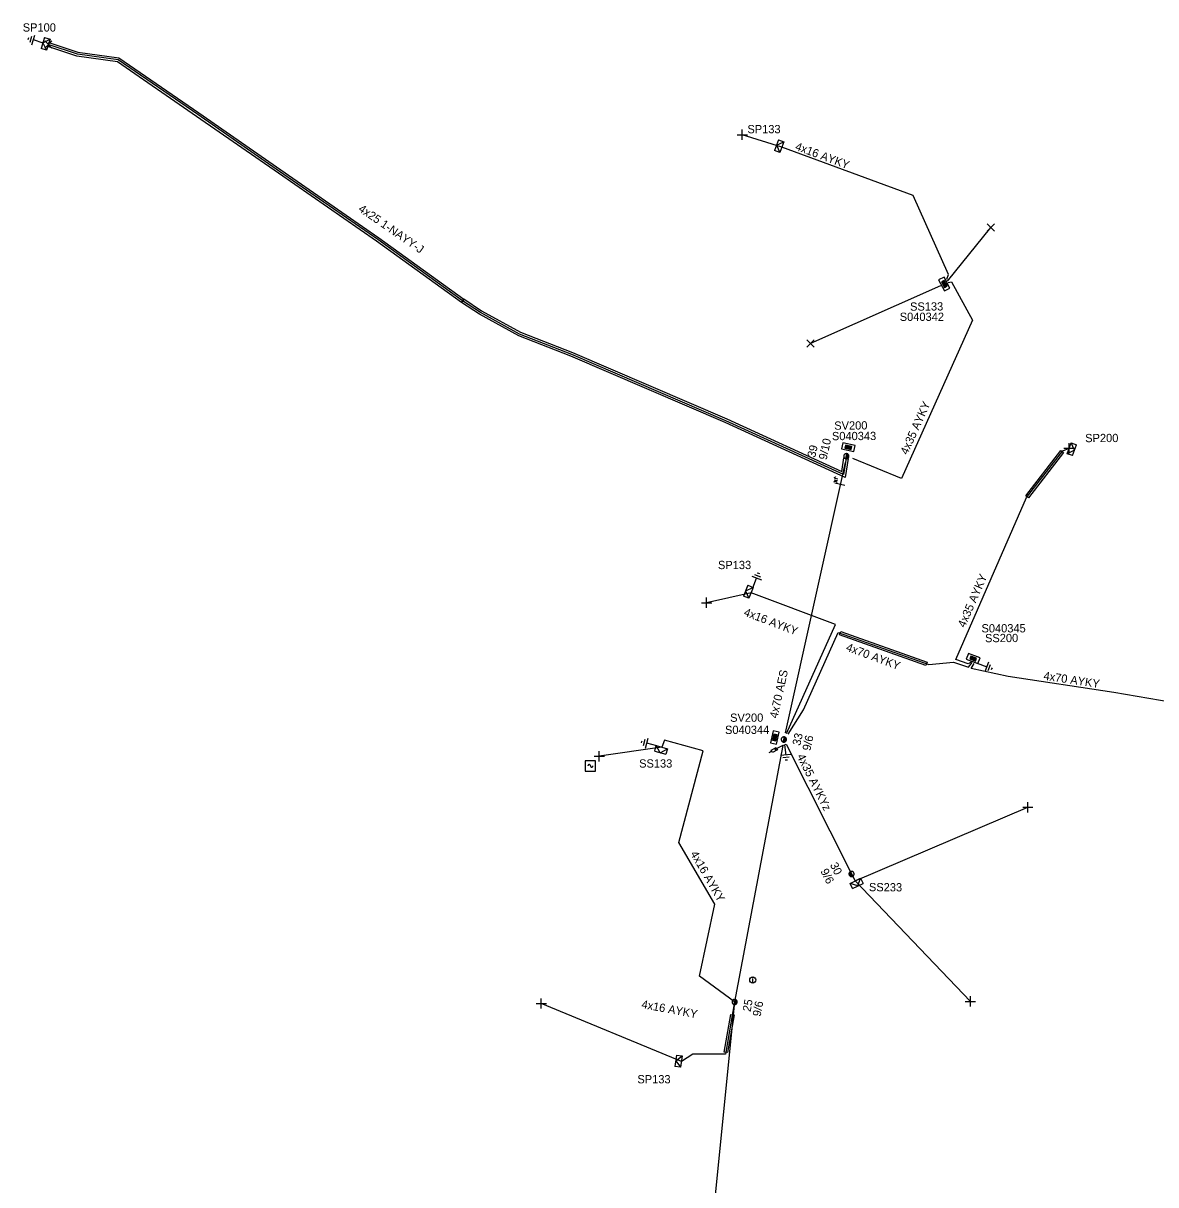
# Model space of a CAD drawing. Extents: x -748492 to -735633, y -1146251 to -1139940.
# Drawn here: x -741038 to -740901, y -1144095.3 to -1143954.7 of the extents above; entities that cross this region are included whole.
import ezdxf

# ---------------------------------------------------------------- set-up
doc = ezdxf.new("R2010")
doc.units = 0
for name, color, linetype in [('Vrstva 1', 7, 'Continuous'), ('Vrstva 10', 7, 'Continuous'), ('Vrstva 12', 7, 'Continuous'), ('Vrstva 13', 7, 'Continuous'), ('Vrstva 14', 7, 'Continuous'), ('Vrstva 15', 7, 'Continuous'), ('Vrstva 16', 7, 'Continuous'), ('Vrstva 18', 7, 'Continuous'), ('Vrstva 2', 7, 'Continuous'), ('Vrstva 20', 7, 'Continuous'), ('Vrstva 28', 7, 'Continuous'), ('Vrstva 29', 7, 'Continuous'), ('Vrstva 30', 7, 'Continuous'), ('Vrstva 31', 7, 'Continuous'), ('Vrstva 33', 7, 'Continuous'), ('Vrstva 34', 7, 'Continuous'), ('Vrstva 36', 7, 'Continuous'), ('Vrstva 5', 7, 'Continuous'), ('Vrstva 50', 7, 'Continuous'), ('Vrstva 51', 7, 'Continuous'), ('Vrstva 52', 7, 'Continuous'), ('Vrstva 54', 7, 'Continuous'), ('Vrstva 55', 7, 'Continuous'), ('Vrstva 59', 7, 'Continuous'), ('Vrstva 6', 7, 'Continuous'), ('Vrstva 8', 7, 'Continuous'), ('Vrstva 9', 7, 'Continuous')]:
    doc.layers.add(name, color=color, linetype=linetype)

# ---------------------------------------------------------------- blocks, each defined once
blk = doc.blocks.new('NN440')
at = {"layer": 'Vrstva 2'}
for points in [[(0.63, 0), (0.63, 0.06), (0.62, 0.13), (0.6, 0.19), (0.58, 0.25), (0.55, 0.31), (0.51, 0.37), (0.47, 0.42), (0.42, 0.46), (0.37, 0.51), (0.32, 0.54), (0.26, 0.57), (0.2, 0.59), (0.13, 0.61), (0.07, 0.62), (0, 0.63), (-0.06, 0.62), (-0.13, 0.61), (-0.19, 0.59), (-0.26, 0.57), (-0.31, 0.54), (-0.37, 0.51), (-0.42, 0.46), (-0.47, 0.42), (-0.51, 0.37), (-0.54, 0.31), (-0.57, 0.25), (-0.6, 0.19), (-0.62, 0.13), (-0.63, 0.06), (-0.63, 0), (-0.63, -0.07), (-0.62, -0.14), (-0.6, -0.2), (-0.57, -0.26), (-0.54, -0.32), (-0.51, -0.37), (-0.47, -0.43), (-0.42, -0.47), (-0.37, -0.51), (-0.31, -0.55), (-0.26, -0.58), (-0.19, -0.6), (-0.13, -0.62), (-0.06, -0.63), (0, -0.63), (0.07, -0.63), (0.13, -0.62), (0.2, -0.6), (0.26, -0.58), (0.32, -0.55), (0.37, -0.51), (0.42, -0.47), (0.47, -0.43), (0.51, -0.37), (0.55, -0.32), (0.58, -0.26), (0.6, -0.2), (0.62, -0.14), (0.63, -0.07), (0.63, 0)], [(-0.63, 0), (0.63, 0)], [(-0.6, -0.18), (0.57, -0.18)], [(-0.51, -0.32), (0.5, -0.32)], [(-0.37, -0.47), (0.35, -0.47)]]:
    blk.add_lwpolyline(points, dxfattribs=at)
blk = doc.blocks.new('NN840')
at = {"layer": 'Vrstva 15'}
for points in [[(0, 0.62), (0, -0.63)], [(-0.75, -0.71), (-0.75, -0.66)], [(-0.73, -0.76), (-0.75, -0.71)], [(-0.66, -0.8), (-0.73, -0.76)], [(-0.63, -0.8), (-0.66, -0.8)], [(-0.56, -0.76), (-0.63, -0.8)], [(-0.54, -0.71), (-0.56, -0.76)], [(-0.54, -0.38), (-0.54, -0.71)], [(-0.33, -0.38), (-0.33, -0.8)], [(-0.33, -0.64), (-0.13, -0.38)], [(-0.26, -0.56), (-0.09, -0.8)]]:
    blk.add_lwpolyline(points, dxfattribs=at)
blk = doc.blocks.new('NN770')
at = {"layer": 'Vrstva 10'}
for p, q in [((0, 0.19), (0, 0.26)), ((0, -0.28), (0, 0.11))]:
    blk.add_line(p, q, dxfattribs=at)
blk.add_circle((0, -0.01), 0.375, dxfattribs=at)
blk = doc.blocks.new('NN800')
at = {"layer": 'Vrstva 1'}
for points in [[(-0.44, 0.44), (0.44, -0.44)], [(-0.44, -0.44), (0.44, 0.44)]]:
    blk.add_lwpolyline(points, dxfattribs=at)
blk = doc.blocks.new('NN820')
at = {"layer": 'Vrstva 13'}
for points in [[(0, 0), (0, -1.05)], [(-0.16, -0.81), (0.16, -0.81)], [(-0.16, -1.47), (-0.16, -0.81)], [(0, -1.05), (-0.06, -0.93)], [(0, -1.05), (0.06, -0.93)], [(0.16, -0.81), (0.16, -1.47)], [(0.16, -1.47), (-0.16, -1.47)], [(0, -1.47), (0, -1.87)]]:
    blk.add_lwpolyline(points, dxfattribs=at)
blk = doc.blocks.new('NN620')
at = {"layer": 'Vrstva 8'}
for points in [[(0.75, 0), (-0.75, 0)], [(-0.75, 0), (-0.75, -0.75)], [(0.75, -0.75), (0.75, 0)], [(-0.75, -0.75), (0.75, -0.75)], [(0.37, -0.18), (-0.38, -0.18)], [(-0.38, -0.18), (-0.38, -0.56)], [(-0.38, -0.56), (0.37, -0.56)], [(0.32, -0.23), (-0.33, -0.23)], [(-0.33, -0.23), (-0.33, -0.51)], [(-0.33, -0.51), (0.32, -0.51)], [(0.27, -0.27), (-0.28, -0.27)], [(-0.28, -0.27), (-0.28, -0.46)], [(-0.28, -0.46), (0.27, -0.46)], [(0.23, -0.32), (-0.23, -0.32)], [(-0.23, -0.32), (-0.23, -0.42)], [(-0.23, -0.42), (0.23, -0.42)], [(-0.19, -0.37), (0.19, -0.37)], [(0.23, -0.42), (0.23, -0.32)], [(0.27, -0.46), (0.27, -0.27)], [(0.32, -0.51), (0.32, -0.23)], [(0.37, -0.56), (0.37, -0.18)]]:
    blk.add_lwpolyline(points, dxfattribs=at)
blk = doc.blocks.new('NN630')
at = {"layer": 'Vrstva 9'}
for points in [[(0, -0.7), (-0.7, 0)], [(-0.7, -0.7), (-0.7, 0), (0.7, 0), (0.7, -0.7)], [(-0.7, -0.7), (0.7, -0.7)], [(0, -0.7), (0.7, 0)]]:
    blk.add_lwpolyline(points, dxfattribs=at)
blk = doc.blocks.new('NN810')
at = {"layer": 'Vrstva 14'}
for points in [[(0, -0.64), (0, -1.89)], [(0.63, -1.89), (-0.62, -1.89)], [(0.39, -2.2), (-0.4, -2.2)], [(0, -2.52), (-0.12, -2.52)], [(0.14, -2.52), (0, -2.52)]]:
    blk.add_lwpolyline(points, dxfattribs=at)
blk = doc.blocks.new('NN740')
at = {"layer": 'Vrstva 1'}
for points in [[(0.62, 0.62), (-0.63, 0.62)], [(-0.63, 0.62), (-0.63, -0.63)], [(0, 0), (0, 0.01), (0, 0.03), (-0.01, 0.05), (-0.01, 0.06), (-0.02, 0.08), (-0.03, 0.09), (-0.04, 0.1), (-0.05, 0.11), (-0.06, 0.12), (-0.08, 0.13), (-0.09, 0.14), (-0.11, 0.14), (-0.12, 0.15), (-0.14, 0.15), (-0.15, 0.15), (-0.17, 0.15), (-0.18, 0.15), (-0.2, 0.15), (-0.21, 0.14), (-0.23, 0.13), (-0.24, 0.12), (-0.26, 0.11), (-0.27, 0.1), (-0.28, 0.09), (-0.29, 0.08), (-0.29, 0.06), (-0.3, 0.05), (-0.3, 0.03), (-0.31, 0.02), (-0.31, 0), (-0.31, 0)], [(0.62, -0.63), (0.62, 0.62)], [(-0.63, -0.63), (0.62, -0.63)], [(0, 0), (0, -0.02), (0, -0.03), (0.01, -0.05), (0.01, -0.06), (0.02, -0.08), (0.03, -0.09), (0.04, -0.1), (0.05, -0.11), (0.06, -0.12), (0.07, -0.13), (0.09, -0.14), (0.1, -0.15), (0.12, -0.15), (0.13, -0.15), (0.15, -0.15), (0.16, -0.15), (0.18, -0.15), (0.19, -0.15), (0.21, -0.14), (0.22, -0.14), (0.24, -0.13), (0.25, -0.12), (0.26, -0.11), (0.27, -0.09), (0.28, -0.08), (0.29, -0.07), (0.29, -0.05), (0.3, -0.04), (0.3, -0.02), (0.3, -0.01), (0.3, -0.01)]]:
    blk.add_lwpolyline(points, dxfattribs=at)

msp = doc.modelspace()

# ---------------------------------------------------------------- linework, layer by layer
at = {"layer": 'Vrstva 20'}
for points in [[(-741034.87, -1143957.09), (-741031.37, -1143958.24), (-741026.41, -1143958.95), (-741016.73, -1143965.6), (-741006.83, -1143972.48), (-740994.95, -1143980.71), (-740984.67, -1143988.13), (-740984.97, -1143988.53), (-740995.23, -1143981.11), (-741007.11, -1143972.9), (-741017.01, -1143966.02), (-741026.59, -1143959.43), (-741031.49, -1143958.72), (-741035.03, -1143957.57)], [(-740984.96, -1143988.54), (-740984.68, -1143988.12), (-740982.54, -1143989.54), (-740977.82, -1143992.13), (-740971.54, -1143994.59), (-740952.87, -1144002.62), (-740938.93, -1144008.99), (-740938.69, -1144007.34), (-740938.19, -1144007.42), (-740938.53, -1144009.73), (-740953.07, -1144003.08), (-740971.72, -1143995.05), (-740978.04, -1143992.59), (-740982.8, -1143989.96)], [(-740912.45, -1144006.46), (-740912.12, -1144006.71), (-740916.36, -1144012.19), (-740916.69, -1144011.93)], [(-740939.07, -1144028.37), (-740928.64, -1144032.06), (-740928.78, -1144032.46), (-740939.21, -1144028.77)], [(-740952.77, -1144079.32), (-740953.18, -1144079.25), (-740952.39, -1144074.7), (-740951.98, -1144074.77)]]:
    msp.add_lwpolyline(points, close=True, dxfattribs=at)
at = {"layer": 'Vrstva 5'}
for points in [[(-740926.08, -1143986.12), (-740925.67, -1143986.06), (-740923.13, -1143990.68), (-740931.74, -1144009.86), (-740937.63, -1144007.41)], [(-740945.44, -1144040.8), (-740943.6, -1144037.83), (-740939.38, -1144028.47), (-740928.4, -1144032.36), (-740925.45, -1144032.06), (-740923.6, -1144032.67), (-740923.17, -1144032.13)], [(-740898.98, -1144036.96), (-740906.04, -1144035.73), (-740918.84, -1144033.79), (-740923.28, -1144032.83), (-740922.92, -1144032.22)]]:
    msp.add_lwpolyline(points, dxfattribs=at)
at = {"layer": 'Vrstva 50'}
for points in [[(-740938.56, -1144007.89), (-740945.79, -1144040.64)], [(-740946.1, -1144042.17), (-740951.92, -1144073.19), (-740955, -1144103.8), (-740965.92, -1144134.26)]]:
    msp.add_lwpolyline(points, dxfattribs=at)
at = {"layer": 'Vrstva 52'}
for points in [[(-740938.44, -1144007.38), (-740938.73, -1144009.36), (-740952.97, -1144002.85), (-740971.63, -1143994.82), (-740977.93, -1143992.36), (-740982.67, -1143989.75), (-740984.82, -1143988.33), (-740995.09, -1143980.91), (-741006.97, -1143972.69), (-741016.87, -1143965.81), (-741026.5, -1143959.19), (-741031.43, -1143958.48), (-741034.95, -1143957.33)], [(-740926.26, -1143985.74), (-740926.03, -1143985.16), (-740930.31, -1143975.61), (-740946.2, -1143969.74)], [(-740923.29, -1144032.08), (-740923.67, -1144032.27), (-740925.16, -1144031.74), (-740916.6, -1144012.14), (-740912.21, -1144006.48), (-740911.45, -1144006.18)], [(-740945.62, -1144040.71), (-740939.73, -1144027.53), (-740949.93, -1144023.67)], [(-740951.92, -1144073.19), (-740956.17, -1144070.06), (-740954.33, -1144061.37), (-740958.65, -1144053.88), (-740955.71, -1144042.82), (-740960.38, -1144041.5), (-740960.72, -1144042.36)], [(-740951.92, -1144073.19), (-740953.02, -1144079.49), (-740956.98, -1144079.53), (-740958.35, -1144080.41)]]:
    msp.add_lwpolyline(points, dxfattribs=at)
at = {"layer": 'Vrstva 54'}
msp.add_lwpolyline([(-740946.1, -1144042.17), (-740945.67, -1144042.01), (-740937.77, -1144057.7), (-740937.32, -1144058.53)], dxfattribs=at)
at = {"layer": 'Vrstva 59'}
for points in [[(-740946.2, -1143969.74), (-740951, -1143968.25)], [(-740926.16, -1143985.97), (-740920.92, -1143979.47)], [(-740927, -1143986.54), (-740942.75, -1143993.5)], [(-740949.93, -1144023.67), (-740955.31, -1144024.88)], [(-740960.72, -1144042.36), (-740968.29, -1144043.46)], [(-740937.32, -1144058.53), (-740916.44, -1144049.63)], [(-740937.32, -1144058.53), (-740923.38, -1144073.13)], [(-740958.35, -1144080.41), (-740975.31, -1144073.38)]]:
    msp.add_lwpolyline(points, dxfattribs=at)

# ---------------------------------------------------------------- block references
at = {"layer": 'Vrstva 13'}
for p, xscale, yscale, rotation in [((-740938.4, -1144007.15), 0.49999999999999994, 0.5000000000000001, 77.56325001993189), ((-740945.96, -1144041.43), 0.5, 0.5000000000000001, 77.47791944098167), ((-740937.77, -1144057.7), 0.5, 0.49999999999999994, -63.49009714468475), ((-740951.92, -1144073.19), 0.49999999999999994, 0.5, 79.23965001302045)]:
    msp.add_blockref('NN440', p, dxfattribs=dict(at, xscale=xscale, yscale=yscale, rotation=rotation))
at = {"layer": 'Vrstva 15'}
for p, rotation in [((-741034.95, -1143957.33), -107.10272893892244), ((-740949.93, -1144023.67), 159.2618165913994), ((-740923.18, -1144031.98), 69.1041722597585), ((-740960.72, -1144042.36), -105.48023333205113), ((-740945.96, -1144041.43), 6.726866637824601)]:
    msp.add_blockref('NN810', p, dxfattribs=dict(at, rotation=rotation))
at = {"layer": 'Vrstva 16', "rotation": -62.72376105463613}
msp.add_blockref('NN820', (-740946.1, -1144042.17), dxfattribs=at)
at = {"layer": 'Vrstva 18', "rotation": -102.52208058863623}
msp.add_blockref('NN840', (-740939.18, -1144010.54), dxfattribs=at)
at = {"layer": 'Vrstva 28'}
for p, rotation in [((-740926.22, -1143986.13), -62.136677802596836), ((-740938.24, -1144006.42), 167.56300003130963), ((-740923.19, -1144031.98), 159.1041722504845), ((-740946.69, -1144041.27), -102.52199995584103)]:
    msp.add_blockref('NN620', p, dxfattribs=dict(at, rotation=rotation))
at = {"layer": 'Vrstva 31'}
for p, rotation in [((-741034.95, -1143957.33), -107.10272893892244), ((-740946.2, -1143969.74), -110.29048888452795), ((-740911.45, -1144006.18), 70.51585554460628), ((-740949.93, -1144023.67), -110.73818336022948), ((-740960.72, -1144042.36), -15.480233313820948), ((-740937.32, -1144058.53), 26.50990267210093), ((-740958.35, -1144080.41), -97.89646669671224)]:
    msp.add_blockref('NN630', p, dxfattribs=dict(at, rotation=rotation))
at = {"layer": 'Vrstva 34'}
for name, p in [('NN800', (-741034.95, -1143957.33)), ('NN800', (-740920.92, -1143979.47)), ('NN800', (-740942.75, -1143993.5)), ('NN740', (-740969.36, -1144044.62))]:
    msp.add_blockref(name, p, dxfattribs=at)
for p, rotation in [((-740951, -1143968.25), 45), ((-740911.45, -1144006.18), 45), ((-740955.31, -1144024.88), 45), ((-740968.29, -1144043.46), 45), ((-740916.44, -1144049.63), 44.99999995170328), ((-740975.31, -1144073.38), 45), ((-740923.38, -1144073.13), 45)]:
    msp.add_blockref('NN800', p, dxfattribs=dict(at, rotation=rotation))
at = {"layer": 'Vrstva 36'}
msp.add_blockref('NN770', (-740949.72, -1144070.52), dxfattribs=at)

# ---------------------------------------------------------------- texts
at = {"layer": 'Vrstva 12'}
for s, rotation, p in [('9/10', 77.563, (-740940.79, -1144007.66)), ('9/6', 77.478, (-740942.76, -1144042.86)), ('9/6', 296.51, (-740941.56, -1144057.35)), ('9/6', 79.24, (-740948.78, -1144075.01))]:
    msp.add_text(s, height=1, rotation=rotation, dxfattribs=at).set_placement(p)
at = {"layer": 'Vrstva 14'}
for s, rotation, p in [('39', 77.563, (-740942.17, -1144007.37)), ('33', 77.478, (-740943.97, -1144042.23)), ('30', 296.51, (-740940.41, -1144056.6)), ('25', 79.24, (-740949.99, -1144074.43))]:
    msp.add_text(s, height=1, rotation=rotation, dxfattribs=at).set_placement(p)
at = {"layer": 'Vrstva 29'}
for s, rotation, p in [('S040342', 359.941, (-740931.94, -1143990.77)), ('S040343', 0.218, (-740940.14, -1144005.21)), ('S040344', 0.157, (-740953.08, -1144040.76))]:
    msp.add_text(s, height=1, rotation=rotation, dxfattribs=at).set_placement(p)
msp.add_text('S040345', height=1, dxfattribs=at).set_placement((-740922.05, -1144028.47))
at = {"layer": 'Vrstva 30'}
for s, rotation, p in [('SS133', 0.406, (-740930.69, -1143989.54)), ('SV200', 0.417, (-740939.86, -1144003.94)), ('SS200', 0.292, (-740921.62, -1144029.66)), ('SV200', 0.131, (-740952.46, -1144039.29))]:
    msp.add_text(s, height=1, rotation=rotation, dxfattribs=at).set_placement(p)
at = {"layer": 'Vrstva 33'}
msp.add_text('SP100', height=1, dxfattribs=at).set_placement((-741038.05, -1143955.76))
for s, rotation, p in [('SP133', 0.094, (-740950.37, -1143968.07)), ('SP200', 0.206, (-740909.5, -1144005.45)), ('SP133', 0.055, (-740953.93, -1144020.81)), ('SS133', 359.98, (-740963.47, -1144044.83)), ('SS233', 359.602, (-740935.67, -1144059.79)), ('SP133', 359.976, (-740963.68, -1144083.04))]:
    msp.add_text(s, height=1, rotation=rotation, dxfattribs=at).set_placement(p)
at = {"layer": 'Vrstva 51'}
msp.add_text('4x70 AES', height=1, rotation=77.565, dxfattribs=at).set_placement((-740946.73, -1144038.93))
at = {"layer": 'Vrstva 54'}
for s, rotation, p in [('4x16 AYKY', 339.71, (-740944.67, -1143970.05)), ('4x25 1-NAYY-J', 325.32, (-740997.53, -1143977.42)), ('4x35 AYKY', 66.404, (-740924.06, -1144027.96)), ('4x16 AYKY', 339.262, (-740950.89, -1144026.41)), ('4x16 AYKY', 299.998, (-740957.31, -1144055.26)), ('4x16 AYKY', 349.451, (-740963.24, -1144073.92))]:
    msp.add_text(s, height=1, rotation=rotation, dxfattribs=at).set_placement(p)
at = {"layer": 'Vrstva 55'}
msp.add_text('4x35 AYKYz', height=1, rotation=296.518, dxfattribs=at).set_placement((-740944.41, -1144043.46))
at = {"layer": 'Vrstva 6'}
for s, rotation, p in [('4x35 AYKY', 65.817, (-740931.01, -1144007.04)), ('4x70 AYKY', 339.765, (-740938.52, -1144030.66)), ('4x70 AYKY', 351.382, (-740914.59, -1144034.18))]:
    msp.add_text(s, height=1, rotation=rotation, dxfattribs=at).set_placement(p)

doc.saveas('drawing.dxf')
